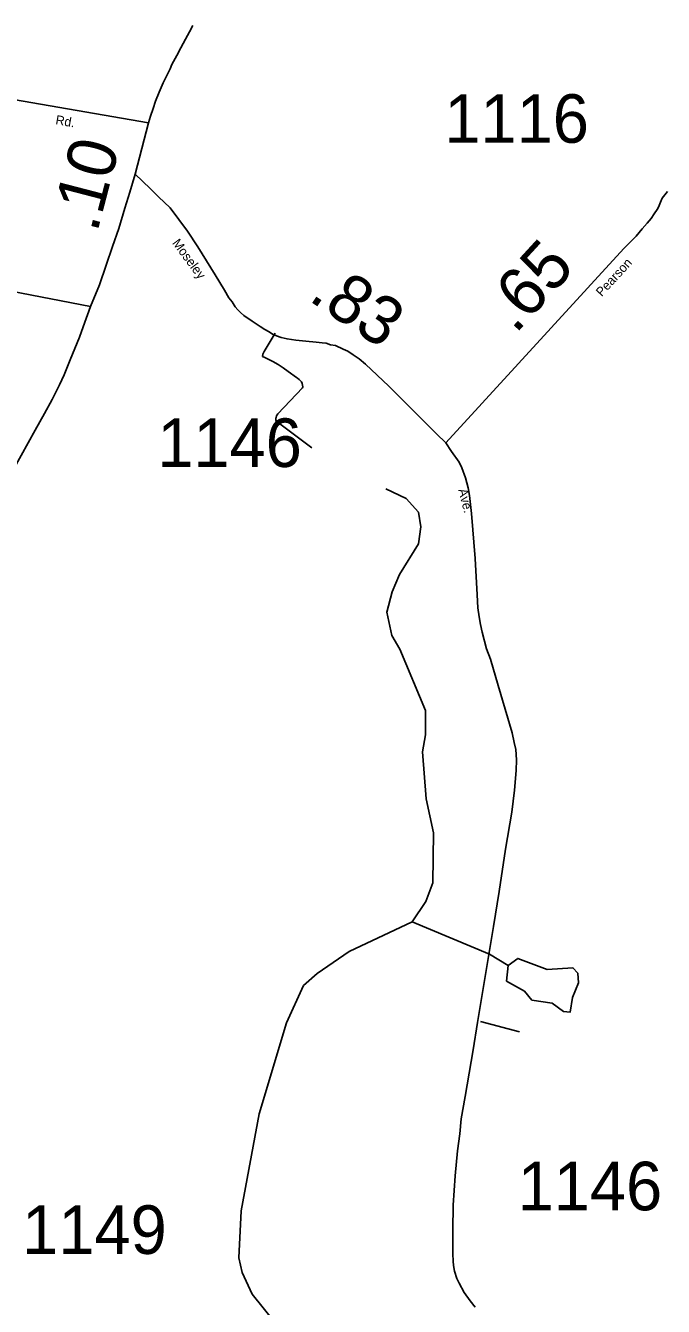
# Model space of a CAD drawing. Extents: x 2093524 to 2270757, y 289120 to 570408.
# Drawn here: x 2202755 to 2209318, y 424769 to 437955 of the extents above; entities that cross this region are included whole.
import ezdxf

# ---------------------------------------------------------------- set-up
doc = ezdxf.new("R2010")
doc.units = 0
for name, color, linetype in [('Exist Hydrographic Creek Single Shore', 7, 'Continuous'), ('Exist Hydrographic Misc Water Feature', 7, 'Continuous'), ('Exist Hydrographic Pond Under 1500 Sq Ft', 7, 'Continuous'), ('Exist Road Non-System Type 51', 7, 'Continuous'), ('Exist Road Primary US Attributed', 7, 'Continuous'), ('Exist Road Primary US Mileage Hundredths English Label', 7, 'Continuous'), ('Exist Road Secondary Mileage Hundredths English Label', 7, 'Continuous'), ('Exist Road Secondary Type 51 Attributed', 7, 'Continuous'), ('Exist Road Secondary Type 51 Label', 7, 'Continuous'), ('Exist Road Secondary Type 51 Number Label', 7, 'Continuous')]:
    doc.layers.add(name, color=color, linetype=linetype)

msp = doc.modelspace()

# ---------------------------------------------------------------- linework, layer by layer
at = {"layer": 'Exist Hydrographic Creek Single Shore'}
for points in [[(2206734, 428728), (2206874, 428939), (2206947, 429131), (2206952, 429646), (2206876, 429995), (2206838, 430478), (2206870, 430654), (2206870, 430904), (2206606, 431535), (2206522, 431675), (2206471, 431918), (2206528, 432127), (2206602, 432303), (2206799, 432620), (2206822, 432794), (2206797, 432945), (2206670, 433085), (2206462, 433185)], [(2207150, 420212), (2207091, 420410), (2207018, 421267), (2206925, 421600), (2206882, 421657), (2206747, 422089), (2206451, 422587), (2205872, 423182), (2205780, 423348), (2205727, 423723), (2205702, 423750), (2205616, 424090), (2205440, 424454), (2205086, 424894), (2204985, 425119), (2204950, 425267), (2204972, 425752), (2205157, 426752), (2205441, 427688), (2205614, 428072), (2205754, 428197), (2206086, 428423), (2206734, 428728)]]:
    msp.add_lwpolyline(points, dxfattribs=at)
at = {"layer": 'Exist Hydrographic Misc Water Feature'}
msp.add_lwpolyline([(2207721, 428279), (2207528, 428394), (2206734, 428728)], dxfattribs=at)
at = {"layer": 'Exist Hydrographic Pond Under 1500 Sq Ft'}
msp.add_lwpolyline([(2207721, 428279), (2207820, 428352), (2208121, 428238), (2208387, 428256), (2208437, 428199), (2208446, 428100), (2208381, 427948), (2208357, 427797), (2208290, 427805), (2208172, 427889), (2207965, 427920), (2207888, 428013), (2207705, 428118), (2207721, 428279)], dxfattribs=at)
at = {"layer": 'Exist Road Non-System Type 51'}
msp.add_line((2207435, 427703), (2207836, 427596), dxfattribs=at)
for points in [[(2202607, 435221), (2203424, 435065)], [(2205701, 433609), (2205342, 433876), (2205335, 433886), (2205329, 433896), (2205330, 433906), (2205331, 433914), (2205333, 433922), (2205337, 433936), (2205351, 433959), (2205603, 434226), (2205607, 434236), (2205601, 434270), (2205593, 434288), (2205569, 434312), (2205552, 434324), (2205544, 434332), (2205456, 434395), (2205406, 434433), (2205354, 434466), (2205299, 434496), (2205265, 434514), (2205217, 434537), (2205193, 434549), (2205193, 434557), (2205195, 434563), (2205197, 434571), (2205211, 434601), (2205323, 434790)]]:
    msp.add_lwpolyline(points, dxfattribs=at)
at = {"layer": 'Exist Road Primary US Attributed'}
msp.add_line((2203883, 436425), (2204021, 436956), dxfattribs=at)
for points in [[(2204021, 436956), (2204040, 437024), (2204066, 437102), (2204091, 437179), (2204129, 437269), (2204150, 437319), (2204172, 437367), (2204208, 437443), (2204241, 437511), (2204259, 437555), (2204310, 437648), (2204352, 437726), (2204401, 437816), (2204442, 437891), (2204476, 437957)], [(2202494, 433139), (2202853, 433789), (2202948, 433960), (2203029, 434106), (2203104, 434257), (2203151, 434359), (2203214, 434514), (2203308, 434746), (2203348, 434854), (2203424, 435065), (2203515, 435285), (2203583, 435488), (2203648, 435680), (2203715, 435865), (2203775, 436075), (2203828, 436239), (2203883, 436425)]]:
    msp.add_lwpolyline(points, dxfattribs=at)
at = {"layer": 'Exist Road Secondary Type 51 Attributed'}
for points in [[(2198735, 437570), (2199148, 437680), (2199214, 437701), (2199264, 437719), (2199318, 437728), (2199354, 437734), (2199394, 437734), (2199456, 437732), (2199501, 437733), (2199554, 437729), (2199672, 437706), (2204021, 436956)], [(2207079, 433661), (2206984, 433754), (2206869, 433865), (2206491, 434243), (2206254, 434471), (2206187, 434525), (2206127, 434566), (2206071, 434604), (2206024, 434625), (2205943, 434661), (2205892, 434670), (2205848, 434686), (2205808, 434690), (2205746, 434695), (2205638, 434707), (2205534, 434716), (2205446, 434729), (2205386, 434745), (2205336, 434760), (2205294, 434778), (2205260, 434804), (2205216, 434828), (2205169, 434859), (2205085, 434911), (2205001, 434972), (2204966, 435002), (2204940, 435028), (2204912, 435061), (2204880, 435111), (2204848, 435153), (2204803, 435232), (2204706, 435390), (2204526, 435679), (2204421, 435838), (2204243, 436078), (2204122, 436192), (2204036, 436279), (2203883, 436425)], [(2209360, 436247), (2209305, 436177), (2209289, 436137), (2209267, 436087), (2209255, 436063), (2209224, 436017), (2209192, 435968), (2209150, 435922), (2209099, 435862), (2209037, 435789), (2208912, 435661), (2207079, 433661)], [(2207382, 424761), (2207330, 424826), (2207267, 424912), (2207215, 425009), (2207194, 425055), (2207169, 425131), (2207159, 425191), (2207155, 425235), (2207152, 425309), (2207151, 425553), (2207155, 425811), (2207175, 426113), (2207199, 426369), (2207222, 426547), (2207237, 426699), (2207279, 426931), (2207360, 427411), (2207406, 427692), (2207569, 428680), (2207629, 429039), (2207693, 429475), (2207759, 429857), (2207785, 430083), (2207802, 430285), (2207807, 430395), (2207798, 430503), (2207784, 430573), (2207761, 430675), (2207618, 431160), (2207540, 431433), (2207499, 431539), (2207452, 431712), (2207436, 431788), (2207423, 431868), (2207410, 431962), (2207403, 432094), (2207381, 432469), (2207344, 432933), (2207323, 433119), (2207308, 433197), (2207281, 433301), (2207243, 433404), (2207216, 433460), (2207139, 433571), (2207079, 433661)]]:
    msp.add_lwpolyline(points, dxfattribs=at)

# ---------------------------------------------------------------- texts
at = {"layer": 'Exist Road Primary US Mileage Hundredths English Label'}
msp.add_text('.10', height=500, rotation=75.4333, dxfattribs=at).set_placement((2203491, 435814))
at = {"layer": 'Exist Road Secondary Mileage Hundredths English Label'}
for s, rotation, p in [('.65', 47.4876, (2207794, 434772)), ('.83', 326.3207, (2205653, 435134))]:
    msp.add_text(s, height=500, rotation=rotation, dxfattribs=at).set_placement(p)
at = {"layer": 'Exist Road Secondary Type 51 Label'}
for s, rotation, p in [('Rd.', 350.2196, (2203058, 436941)), ('Moseley', 306.4173, (2204259, 435716)), ('Pearson', 47.4876, (2208683, 435159)), ('Ave.', 284.4647, (2207206, 433176))]:
    msp.add_text(s, height=95, rotation=rotation, dxfattribs=at).set_placement(p)
at = {"layer": 'Exist Road Secondary Type 51 Number Label'}
for s, p in [('1116', (2207064, 436749)), ('1146', (2204110, 433411)), ('1146', (2207818, 425758)), ('1149', (2202720, 425309))]:
    msp.add_text(s, height=500, dxfattribs=at).set_placement(p)

doc.saveas('drawing.dxf')
